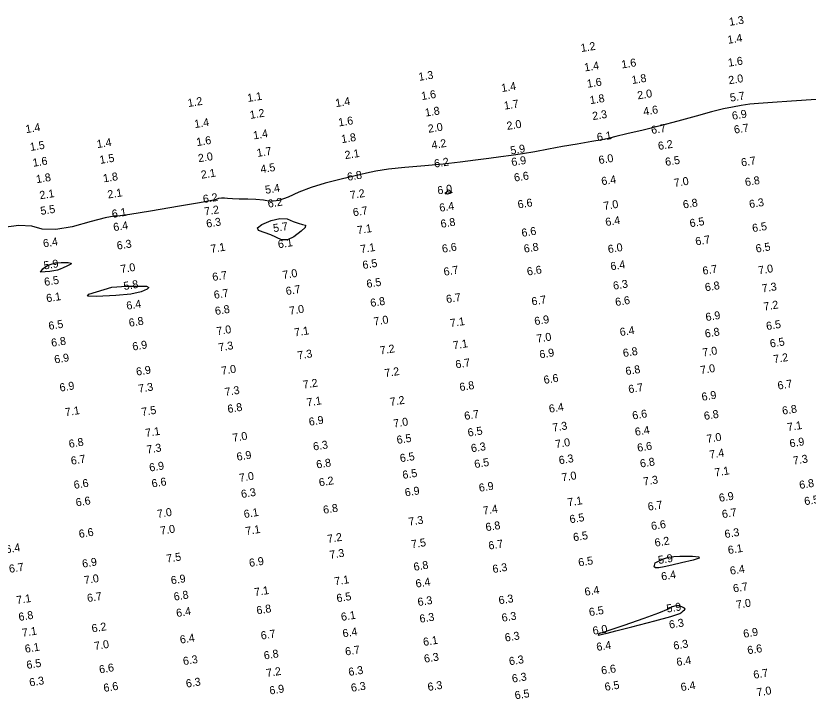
# Model space of a CAD drawing. Extents: x 988130 to 1132882, y 654656 to 841453.
# Drawn here: x 1105767.2 to 1106262.2, y 666273.4 to 666698.7 of the extents above; entities that cross this region are included whole.
import ezdxf

# ---------------------------------------------------------------- set-up
doc = ezdxf.new("R2010")
doc.units = 0
doc.layers.add('V-TOPO-MINR', color=7, linetype='Continuous')
doc.layers.add('V-TOPO-SOUN', color=7, linetype='Continuous')

msp = doc.modelspace()

# ---------------------------------------------------------------- linework, layer by layer
at = {"layer": 'V-TOPO-MINR'}
msp.add_lwpolyline([(1106267.16, 666646.43), (1106251.87, 666645.44), (1106239.89, 666644.6), (1106231.21, 666643.91), (1106225.84, 666643.37), (1106220.4, 666642.61), (1106214.88, 666641.64), (1106209.29, 666640.46), (1106201.74, 666638.6), (1106192.23, 666636.05), (1106180.77, 666632.81), (1106169.75, 666629.87), (1106159.17, 666627.24), (1106149.03, 666624.9), (1106141.98, 666623.24), (1106138.03, 666622.26), (1106137.17, 666621.96), (1106133.51, 666621.23), (1106127.06, 666620.09), (1106117.82, 666618.52), (1106108.81, 666616.94), (1106100.04, 666615.35), (1106091.51, 666613.75), (1106083.7, 666612.42), (1106076.61, 666611.35), (1106070.23, 666610.54), (1106062.79, 666609.57), (1106054.29, 666608.43), (1106044.72, 666607.13), (1106034.18, 666605.94), (1106022.67, 666604.85), (1106010.2, 666603.86), (1105999.98, 666602.77), (1105992.01, 666601.58), (1105986.28, 666600.29), (1105979.12, 666598.62), (1105970.53, 666596.57), (1105960.5, 666594.15), (1105951.64, 666591.46), (1105943.95, 666588.5), (1105937.42, 666585.28), (1105931.56, 666583.35), (1105926.38, 666582.72), (1105921.88, 666583.38), (1105917.11, 666583.84), (1105912.09, 666584.1), (1105906.81, 666584.16), (1105902.61, 666584.29), (1105899.51, 666584.5), (1105897.5, 666584.77), (1105895.63, 666584.78), (1105893.9, 666584.51), (1105892.32, 666583.97), (1105890.92, 666583.54), (1105889.7, 666583.22), (1105888.65, 666583), (1105881.92, 666581.82), (1105869.48, 666579.71), (1105851.35, 666576.64), (1105838.49, 666574.59), (1105830.91, 666573.57), (1105828.61, 666573.57), (1105823.07, 666572.43), (1105814.29, 666570.14), (1105802.28, 666566.71), (1105792.08, 666565.07), (1105783.68, 666565.24), (1105777.1, 666567.21), (1105769.06, 666567.61), (1105759.57, 666566.44)], dxfattribs=at)
for points in [[(1106036.16, 666587.95), (1106036.87, 666589.59), (1106037.3, 666589.94), (1106037.83, 666589.81), (1106038.44, 666589.21), (1106038.94, 666588.78), (1106039.33, 666588.54), (1106039.61, 666588.48), (1106039.55, 666588.3), (1106039.13, 666588.01), (1106038.37, 666587.61), (1106037.6, 666587.37), (1106036.81, 666587.28), (1106036.01, 666587.35), (1106035.58, 666587.45), (1106035.52, 666587.59)], [(1105926.55, 666561.77), (1105918.74, 666564.45), (1105918.13, 666566.18), (1105920.81, 666568.3), (1105926.78, 666570.81), (1105932.04, 666571.96), (1105936.61, 666571.74), (1105940.47, 666570.16), (1105943.68, 666568.99), (1105946.25, 666568.22), (1105948.17, 666567.86), (1105947.93, 666566.46), (1105945.53, 666564.02), (1105940.97, 666560.54), (1105936.83, 666558.75), (1105933.12, 666558.63)], [(1105782.53, 666538.38), (1105784.13, 666540.54), (1105785.37, 666541.58), (1105787.05, 666542.59), (1105789.16, 666543.55), (1105792, 666544.21), (1105795.56, 666544.55), (1105799.85, 666544.57), (1105801.85, 666544.18), (1105801.59, 666543.37), (1105799.04, 666542.13), (1105796.79, 666541.11), (1105794.82, 666540.3), (1105793.13, 666539.69), (1105791.02, 666539.21), (1105788.47, 666538.85)], [(1105827.18, 666529.02), (1105836.37, 666529.65), (1105840.75, 666529.81), (1105844.91, 666529.8), (1105848.86, 666529.63), (1105850.27, 666528.96), (1105849.14, 666527.77), (1105845.47, 666526.08), (1105838.98, 666524.75), (1105829.69, 666523.8), (1105817.58, 666523.21), (1105811.92, 666523.53), (1105812.71, 666524.76)], [(1106166.64, 666356.77), (1106171.88, 666359.36), (1106174.9, 666360.28), (1106178.3, 666360.83), (1106182.08, 666361.01), (1106185.94, 666361.03), (1106189.87, 666360.88), (1106193.86, 666360.56), (1106194.05, 666359.77), (1106190.44, 666358.5), (1106183.03, 666356.74), (1106176.98, 666355.34), (1106172.3, 666354.29), (1106168.98, 666353.59), (1106166.87, 666353.56), (1106165.98, 666354.19)], [(1106134.65, 666312.34), (1106136.56, 666312.84), (1106142.01, 666314.24), (1106151.97, 666316.78), (1106166.42, 666320.47), (1106176.46, 666323.23), (1106182.08, 666325.07), (1106183.29, 666325.98), (1106184.23, 666326.74), (1106184.91, 666327.34), (1106185.32, 666327.8), (1106184.94, 666328.38), (1106183.77, 666329.07), (1106181.79, 666329.87), (1106179.62, 666329.92), (1106177.25, 666329.21), (1106174.69, 666327.75), (1106168.8, 666325.33), (1106159.57, 666321.96), (1106147, 666317.64), (1106138.31, 666314.68), (1106133.48, 666313.08), (1106132.52, 666312.85), (1106131.78, 666312.56), (1106131.26, 666312.22), (1106130.96, 666311.83), (1106131.2, 666311.67), (1106131.99, 666311.74)]]:
    msp.add_lwpolyline(points, close=True, dxfattribs=at)

# ---------------------------------------------------------------- texts
at = {"layer": 'V-TOPO-SOUN'}
for s, p in [('1.3', (1106213.18, 666692.4)), ('1.4', (1106212.23, 666681.16)), ('1.2', (1106120.5, 666676.05)), ('1.4', (1106122.7, 666663.91)), ('1.6', (1106145.93, 666665.77)), ('1.6', (1106212.55, 666666.86)), ('1.3', (1106019.16, 666658.02)), ('1.8', (1106152.33, 666656.04)), ('2.0', (1106212.8, 666655.88)), ('1.4', (1106070.83, 666651.04)), ('1.6', (1106124.36, 666653.7)), ('1.1', (1105912.15, 666644.82)), ('1.6', (1106020.85, 666646.01)), ('2.0', (1106155.88, 666646.47)), ('5.7', (1106213.73, 666645.02)), ('1.2', (1105874.93, 666641.67)), ('1.4', (1105967.22, 666641.63)), ('1.7', (1106072.53, 666640.02)), ('1.8', (1106126.14, 666643.46)), ('1.2', (1105913.73, 666634.26)), ('1.8', (1106023.17, 666635.67)), ('4.6', (1106159.59, 666636.38)), ('1.6', (1105969.07, 666629.53)), ('2.3', (1106127.71, 666633.51)), ('6.9', (1106215.02, 666633.7)), ('1.4', (1105773.6, 666625.34)), ('1.4', (1105879.07, 666628.5)), ('2.0', (1106025.06, 666625.55)), ('2.0', (1106074.23, 666627.36)), ('6.7', (1106164.49, 666624.78)), ('6.7', (1106216.27, 666625.03)), ('1.4', (1105915.83, 666621.43)), ('6.1', (1106130.62, 666620.28)), ('1.4', (1105818.12, 666615.98)), ('1.6', (1105880.38, 666617.24)), ('1.8', (1105970.85, 666619.09)), ('4.2', (1106027.29, 666615.38)), ('6.2', (1106168.82, 666614.81)), ('1.5', (1105776.35, 666614.2)), ('1.7', (1105918.13, 666610.47)), ('5.9', (1106076.53, 666612.02)), ('1.5', (1105819.9, 666606.12)), ('2.0', (1105881.42, 666607.14)), ('2.1', (1105973.04, 666609.1)), ('6.9', (1106077.15, 666604.74)), ('6.0', (1106131.65, 666606.02)), ('6.5', (1106173.24, 666604.85)), ('6.7', (1106220.7, 666604.51)), ('1.6', (1105778.1, 666604.32)), ('4.5', (1105920.4, 666600.33)), ('6.2', (1106028.91, 666603.78)), ('1.8', (1105822.09, 666594.58)), ('2.1', (1105883.21, 666596.84)), ('6.8', (1105974.57, 666595.55)), ('6.6', (1106078.85, 666595.04)), ('1.8', (1105780.19, 666594.06)), ('6.4', (1106133.39, 666592.78)), ('7.0', (1106178.72, 666591.72)), ('6.8', (1106223.15, 666592.2)), ('5.4', (1105923.31, 666587.42)), ('6.0', (1106030.96, 666586.98)), ('2.1', (1105782.36, 666584)), ('2.1', (1105824.85, 666584.47)), ('6.2', (1105884.46, 666581.62)), ('7.2', (1105976.36, 666584.09)), ('6.2', (1105924.94, 666578.74)), ('6.4', (1106032.17, 666576.18)), ('6.6', (1106081.12, 666578.25)), ('7.0', (1106134.74, 666577.31)), ('6.8', (1106184.36, 666578.22)), ('6.3', (1106225.72, 666578.45)), ('5.5', (1105782.9, 666574.2)), ('6.1', (1105827.52, 666572.35)), ('7.2', (1105885.31, 666573.88)), ('6.7', (1105978.16, 666573.34)), ('6.3', (1105886.52, 666566.25)), ('6.8', (1106032.96, 666566.14)), ('6.4', (1106135.9, 666567.25)), ('6.5', (1106188.56, 666566.5)), ('6.4', (1105828.45, 666564.05)), ('5.7', (1105928.34, 666563.44)), ('7.1', (1105980.78, 666562.16)), ('6.6', (1106083.49, 666560.5)), ('6.5', (1106227.62, 666563.46)), ('6.7', (1106192.13, 666555.18)), ('6.4', (1105784.57, 666553.93)), ('6.3', (1105830.65, 666552.52)), ('7.1', (1105889.22, 666550.51)), ('6.1', (1105931.29, 666553.35)), ('7.1', (1105982.85, 666550.33)), ('6.6', (1106033.81, 666550.57)), ('6.8', (1106084.94, 666550.61)), ('6.0', (1106137.44, 666550.32)), ('6.5', (1106229.84, 666550.68)), ('5.9', (1105785.01, 666540.13)), ('6.5', (1105984.17, 666540.4)), ('7.0', (1105832.96, 666537.86)), ('6.7', (1106034.86, 666536.19)), ('6.6', (1106086.9, 666536.31)), ('6.4', (1106139.08, 666539.59)), ('6.7', (1106196.61, 666536.79)), ('7.0', (1106231.46, 666537.07)), ('6.7', (1105890.31, 666532.91)), ('7.0', (1105934.21, 666534.17)), ('6.5', (1105785.28, 666529.84)), ('5.8', (1105834.85, 666527.28)), ('6.5', (1105986.63, 666528.61)), ('6.3', (1106140.72, 666527.47)), ('6.8', (1106198.1, 666526.47)), ('7.3', (1106233.7, 666525.75)), ('6.7', (1105891.26, 666521.75)), ('6.7', (1105936.22, 666524.12)), ('6.1', (1105786.54, 666519.63)), ('6.8', (1105989.05, 666516.7)), ('6.7', (1106036.4, 666519.08)), ('6.7', (1106089.77, 666517.63)), ('6.6', (1106142.04, 666517.26)), ('6.4', (1105836.63, 666514.95)), ('6.8', (1105891.97, 666511.66)), ('7.0', (1105938.4, 666511.78)), ('7.2', (1106234.75, 666514.43)), ('6.9', (1106198.5, 666507.84)), ('6.5', (1105787.95, 666502.38)), ('6.8', (1105838.13, 666504.3)), ('7.0', (1105991.14, 666505.1)), ('7.1', (1106038.84, 666504.06)), ('6.9', (1106091.54, 666505.3)), ('6.5', (1106236.36, 666502.24)), ('7.0', (1105892.9, 666499.02)), ('7.1', (1105941.53, 666498.25)), ('6.4', (1106144.9, 666498.49)), ('6.8', (1106198.05, 666497.52)), ('6.8', (1105789.63, 666491.79)), ('7.0', (1106092.91, 666494.38)), ('6.5', (1106238.69, 666491.32)), ('6.9', (1105840.38, 666489.44)), ('7.3', (1105894.16, 666488.92)), ('7.2', (1105995.03, 666486.99)), ('7.1', (1106040.72, 666490.17)), ('7.0', (1106196.55, 666485.7)), ('6.9', (1105791.58, 666481.39)), ('7.3', (1105943.52, 666483.87)), ('6.9', (1106094.69, 666484.51)), ('6.8', (1106146.86, 666485.37)), ('7.2', (1106240.9, 666481.56)), ('6.7', (1106042.22, 666478.27)), ('6.9', (1105842.7, 666473.74)), ('7.0', (1105895.92, 666474.3)), ('7.2', (1105997.92, 666472.81)), ('6.8', (1106148.45, 666474.08)), ('7.0', (1106195.23, 666474.72)), ('6.6', (1106097.35, 666468.6)), ('6.9', (1105794.88, 666463.79)), ('7.3', (1105844.13, 666463.1)), ('7.3', (1105898.09, 666461.03)), ('7.2', (1105946.91, 666465.58)), ('6.8', (1106044.73, 666464.1)), ('6.7', (1106150.27, 666462.78)), ('6.7', (1106243.5, 666465.05)), ('6.9', (1106196.03, 666458.02)), ('7.1', (1105949.32, 666454.49)), ('7.2', (1106001.25, 666454.83)), ('7.1', (1105798.27, 666448.39)), ('7.5', (1105846.03, 666448.57)), ('6.8', (1105899.8, 666450.44)), ('6.7', (1106047.75, 666446.07)), ('6.4', (1106100.63, 666450.56)), ('6.6', (1106152.73, 666446.33)), ('6.8', (1106197.49, 666446.07)), ('6.8', (1106246.34, 666449.35)), ('6.9', (1105950.61, 666442.41)), ('7.0', (1106003.45, 666441.31)), ('7.3', (1106102.86, 666438.78)), ('7.1', (1106249.52, 666439.06)), ('7.1', (1105848.45, 666435.43)), ('7.0', (1105902.96, 666432.42)), ('6.5', (1106049.9, 666435.65)), ('6.4', (1106154.33, 666436.15)), ('7.0', (1106199.16, 666431.75)), ('6.8', (1105800.64, 666428.63)), ('6.3', (1105953.29, 666426.95)), ('6.5', (1106005.53, 666431.06)), ('7.0', (1106104.63, 666428.45)), ('6.9', (1106250.98, 666428.89)), ('7.3', (1105849.27, 666425.05)), ('6.3', (1106051.94, 666425.85)), ('6.6', (1106155.82, 666426.17)), ('7.4', (1106200.91, 666421.9)), ('6.7', (1105801.94, 666418.07)), ('6.9', (1105905.5, 666420.56)), ('6.5', (1106007.51, 666419.65)), ('6.3', (1106106.8, 666418.37)), ('7.3', (1106253.15, 666418.15)), ('6.9', (1105850.92, 666413.8)), ('6.8', (1105955.27, 666415.71)), ('6.5', (1106054.03, 666415.98)), ('6.8', (1106157.55, 666416.31)), ('7.0', (1105907.06, 666407.36)), ('6.5', (1106009.1, 666409.2)), ('7.0', (1106108.61, 666407.65)), ('7.1', (1106204.13, 666410.72)), ('6.6', (1105803.75, 666402.97)), ('6.6', (1105852.41, 666403.84)), ('6.2', (1105956.91, 666404.52)), ('7.3', (1106159.55, 666405.07)), ('6.8', (1106257.04, 666402.92)), ('6.3', (1105908.27, 666397.25)), ('6.9', (1106010.58, 666398.22)), ('6.9', (1106056.87, 666401.15)), ('6.6', (1105805, 666391.99)), ('7.1', (1106112.24, 666392.03)), ('6.9', (1106206.86, 666394.87)), ('6.5', (1106260.16, 666392.76)), ('6.8', (1105959.55, 666387.38)), ('7.4', (1106059.41, 666386.87)), ('6.7', (1106162.39, 666389.37)), ('7.0', (1105855.81, 666384.83)), ('6.1', (1105909.98, 666384.74)), ('6.7', (1106208.73, 666384.66)), ('7.3', (1106012.9, 666379.92)), ('6.5', (1106113.55, 666381.49)), ('6.6', (1106164.46, 666377.22)), ('6.6', (1105806.89, 666372.33)), ('7.0', (1105857.79, 666374.35)), ('7.1', (1105911.03, 666374.1)), ('6.8', (1106061.04, 666376.53)), ('6.3', (1106210.36, 666372.23)), ('7.2', (1105962.16, 666369.18)), ('6.5', (1106115.76, 666370.24)), ('6.2', (1106166.68, 666366.86)), ('6.4', (1105761.07, 666362.69)), ('7.5', (1106014.55, 666365.84)), ('6.7', (1106062.83, 666365.02)), ('6.1', (1106212.45, 666362.23)), ('7.3', (1105963.55, 666359.25)), ('6.9', (1105808.99, 666353.72)), ('7.5', (1105861.62, 666356.87)), ('6.9', (1105913.29, 666354.2)), ('6.5', (1106118.99, 666354.49)), ('5.9', (1106168.85, 666356.03)), ('6.7', (1105763.3, 666350.48)), ('6.8', (1106016.1, 666351.74)), ('6.3', (1106065.38, 666350.38)), ('6.4', (1106213.75, 666349.31)), ('7.0', (1105810.19, 666343.42)), ('6.9', (1105864.41, 666343.29)), ('7.1', (1105966.61, 666342.68)), ('6.4', (1106170.77, 666345.75)), ('6.4', (1106017.33, 666341.26)), ('6.7', (1106215.67, 666338.28)), ('6.7', (1105812.07, 666332.22)), ('6.8', (1105866.22, 666333.12)), ('7.1', (1105916.51, 666335.92)), ('6.4', (1106122.91, 666336.15)), ('7.1', (1105767.89, 666330.93)), ('6.5', (1105967.92, 666332.15)), ('6.3', (1106018.58, 666329.74)), ('6.3', (1106069.21, 666330.79)), ('7.0', (1106217.6, 666328.09)), ('6.4', (1105867.74, 666322.87)), ('6.8', (1105917.9, 666324.53)), ('6.5', (1106125.67, 666323.44)), ('5.9', (1106174.1, 666325.65)), ('6.8', (1105769.24, 666320.44)), ('6.1', (1105970.73, 666320.46)), ('6.3', (1106019.78, 666319.3)), ('6.3', (1106071.11, 666319.92)), ('6.2', (1105814.93, 666313.25)), ('6.3', (1106175.7, 666315.65)), ('7.1', (1105771.44, 666310.52)), ('6.7', (1105920.6, 666308.79)), ('6.4', (1105971.71, 666310.13)), ('6.3', (1106073.07, 666307.52)), ('6.0', (1106127.96, 666311.81)), ('6.9', (1106222.06, 666309.9)), ('6.4', (1105870.06, 666306.24)), ('6.1', (1106022.03, 666304.79)), ('6.1', (1105773.16, 666300.52)), ('7.0', (1105816.52, 666302.27)), ('6.7', (1105973.3, 666298.81)), ('6.4', (1106130.3, 666301.67)), ('6.3', (1106178.41, 666302.49)), ('6.6', (1106224.61, 666299.6)), ('6.3', (1105872, 666292.8)), ('6.8', (1105922.49, 666296.33)), ('6.3', (1106022.6, 666294.32)), ('6.3', (1106075.7, 666292.71)), ('6.5', (1105774.18, 666290.43)), ('6.6', (1105819.6, 666287.65)), ('6.4', (1106180.3, 666292.24)), ('7.2', (1105923.99, 666285.36)), ('6.3', (1105975.35, 666286.04)), ('6.6', (1106133.27, 666286.95)), ('6.7', (1106228.38, 666284.29)), ('6.3', (1105775.98, 666279.49)), ('6.3', (1105873.82, 666278.78)), ('6.3', (1106077.5, 666281.91)), ('6.6', (1105822.33, 666276.06)), ('6.9', (1105926, 666274.43)), ('6.3', (1105976.95, 666276.13)), ('6.3', (1106024.83, 666276.67)), ('6.5', (1106135.46, 666276.73)), ('6.4', (1106182.97, 666276.58)), ('7.0', (1106230.41, 666273.28)), ('6.5', (1106079.26, 666271.44))]:
    msp.add_text(s, height=5, rotation=9.0039, dxfattribs=at).set_placement(p)

doc.saveas('drawing.dxf')
